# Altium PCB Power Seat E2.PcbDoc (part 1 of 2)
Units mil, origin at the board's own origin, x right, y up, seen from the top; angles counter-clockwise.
Board outline 6560 x 2560 mil, 2 copper layers (Top Layer, Bottom Layer), stack 61.4 mil thick; 98 components, 83 nets, 370 pads, 533 vias.
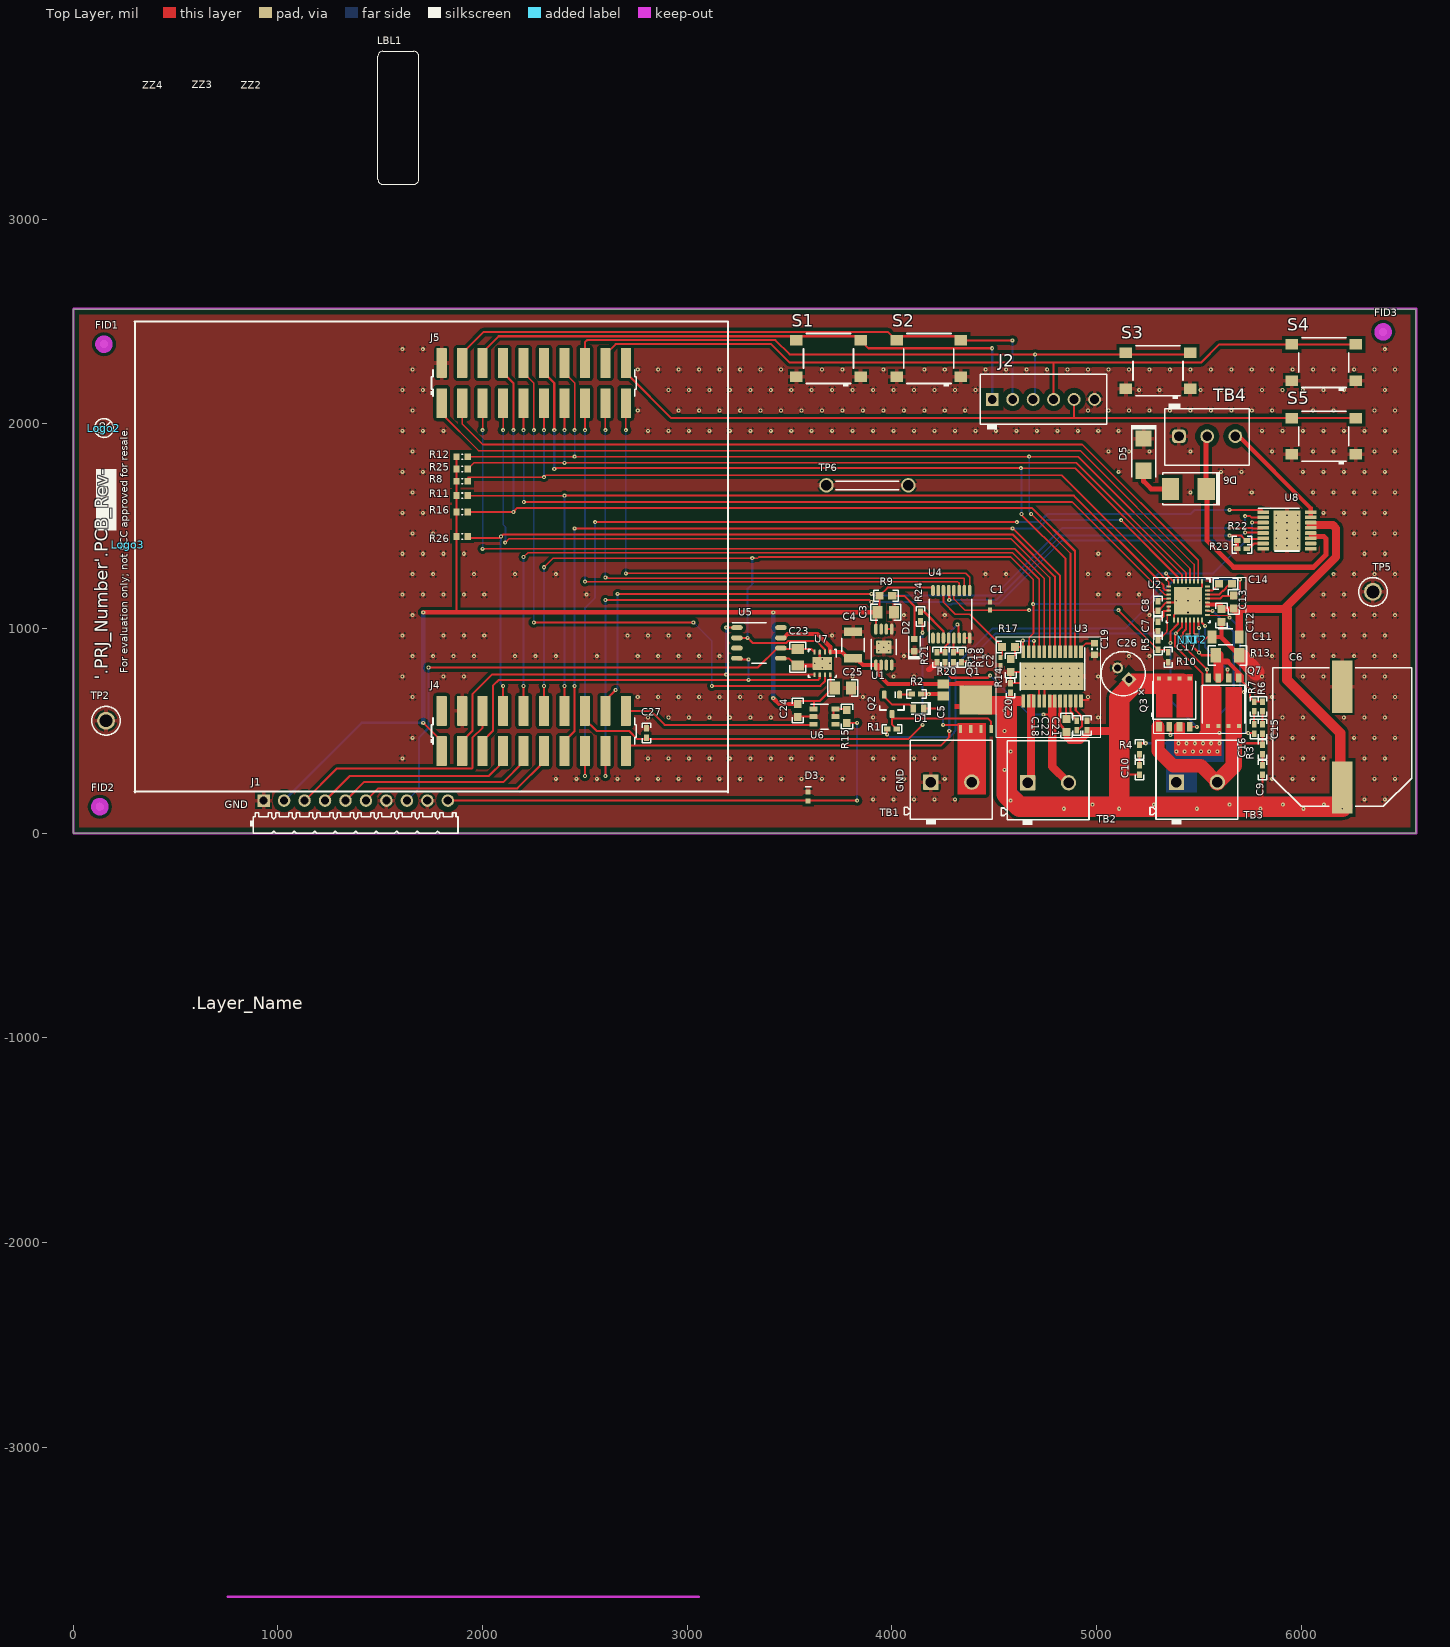
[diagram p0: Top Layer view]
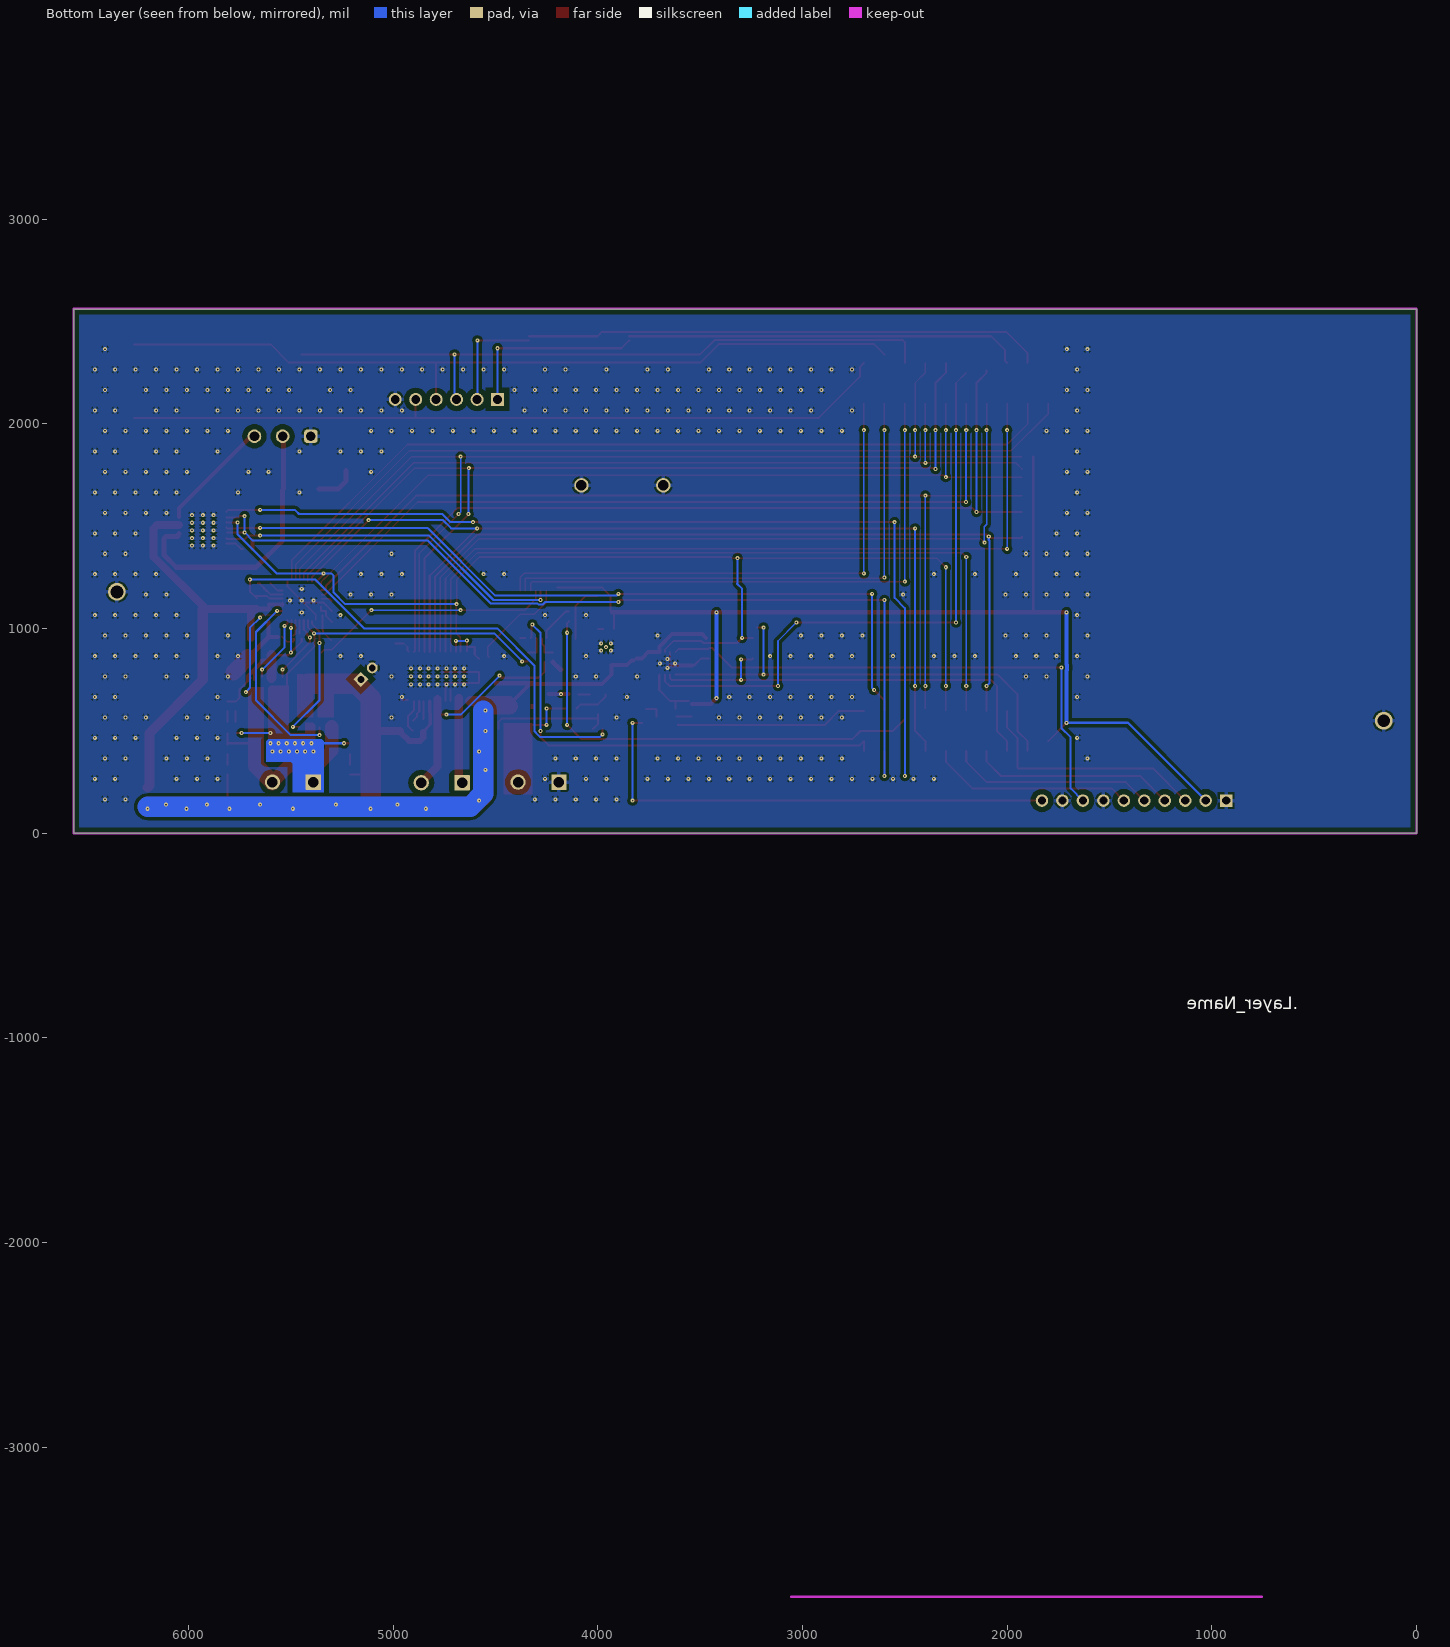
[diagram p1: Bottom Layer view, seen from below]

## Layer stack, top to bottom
Top Solder: solder mask 0.4, Solder Resist, Dk 3.5
Top Layer: signal copper 4.2
Dielectric1: core 53, FR-4, Dk 4.8
Bottom Layer: signal copper 4.2
Bottom Solder: solder mask 0.4, Solder Resist, Dk 3.5

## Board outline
0,0 0,2560 6560,2560 6560,0

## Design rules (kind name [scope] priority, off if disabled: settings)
AcuteAngle [All] p1: minimum=4.50000000000000E+0001 checktracksonly=FALSE
AssemblyTestPointUsage [All] p1: valid=2
BoardOutlineClearance BoardOutlineClearance_MountingHoles [OnCopper and InComponentClass('Mounting Holes')] p1: gap=40 ignorepadtopadclearanceinfootprint=FALSE
BoardOutlineClearance BoardOutlineClearance_Poly [OnCopper and IsPoly] p2: gap=25 ignorepadtopadclearanceinfootprint=FALSE
BoardOutlineClearance [OnCopper and Not InComponentClass('Logo') and not InComponentClass('FiducialMark') and not InRegion(1000,500,4000,800) and not InPoly] p3: gap=75 ignorepadtopadclearanceinfootprint=FALSE
Clearance Clearance_Keepouts [((IsTrack Or IsArc) And Not InPoly) And IsFree and IsKeepOut vs ((IsTrack Or IsArc) And Not InPoly) And IsFree and IsKeepOut] p1: gap=0 ignorepadtopadclearanceinfootprint=FALSE
Clearance Clearance_Poly [InPolygon] p2: gap=25 ignorepadtopadclearanceinfootprint=FALSE except(0: Arc-Hole Track-Hole SMDPad-Hole THPad-Hole Via-Hole Fill-Hole Poly-Hole Region-Hole Text-Hole; 15: Arc-Poly Track-Poly SMDPad-Poly Via-Poly Fill-Poly Poly-Poly)
Clearance [All] p3: gap=7.87 ignorepadtopadclearanceinfootprint=FALSE except(0: Arc-Hole Track-Hole SMDPad-Hole THPad-Hole Via-Hole Fill-Hole Poly-Hole Region-Hole Text-Hole)
ComponentClearance ComponentClearance_MountingHoles_FiducialMarks [InComponentClass('Mounting Holes') vs InComponentClass('FiducialMark')] p1: gap=50 collisioncheckmode=3 verticalgap=10 showdistances=FALSE
ComponentClearance ComponentClearance_Shunt [InComponentClass('Header') vs InComponentClass('Shunt')] p2: gap=0 collisioncheckmode=3 verticalgap=0 showdistances=FALSE
ComponentClearance ComponentClearance_Logo [InComponentClass('Logo')] p3: gap=50 collisioncheckmode=3 verticalgap=10 showdistances=FALSE
ComponentClearance ComponentClearance_ScrewToNut [(HasFootprint('NY PMS 440 0025 PH')) vs (HasFootprint('Keystone_1902C'))] p4: gap=5 collisioncheckmode=3 verticalgap=10 showdistances=FALSE
ComponentClearance ComponentClearance_MountingHoles [InComponentClass('Mounting Holes')] p5: gap=250 collisioncheckmode=3 verticalgap=100000 showdistances=FALSE
ComponentClearance ComponentClearance_SmallPassives [HasFootprint('0201*') or HasFootprint('0402*') or HasFootprint('0508') or HasFootprint('0603*') or HasFootprint('0612') or HasFootprint('0805*') or HasFootprint('0815*') or HasFootprint('0830*') or HasFootprint('1206*') or HasFootprint('1210*') or HasFootprint('1808*') or HasFootprint('1812*') or HasFootprint('1825*') or HasFootprint('2010*') or HasFootprint('2220*') or HasFootprint('2225*') or HasFootprint('2512*') or HasFootprint('2728*') or HasFootprint('3518*') vs HasFootprint('0201*') or HasFootprint('0402*') or HasFootprint('0508') or HasFootprint('0603*') or HasFootprint('0612') or HasFootprint('0805*') or HasFootprint('0815*') or HasFootprint('0830*') or HasFootprint('1206*') or HasFootprint('1210*') or HasFootprint('1808*') or HasFootprint('1812*') or HasFootprint('1825*') or HasFootprint('2010*') or HasFootprint('2220*') or HasFootprint('2225*') or HasFootprint('2512*') or HasFootprint('2728*') or HasFootprint('3518*')] p6: gap=14.96 collisioncheckmode=3 verticalgap=10 showdistances=FALSE
ComponentClearance ComponentClearance_THtoSMT [IsThruComponent vs IsSMTComponent] p7: gap=40 collisioncheckmode=3 verticalgap=30 showdistances=FALSE
ComponentClearance ComponentClearance_THtoTH [IsThruComponent vs IsThruComponent] p8: gap=30 collisioncheckmode=3 verticalgap=30 showdistances=FALSE
ComponentClearance [All] p9: gap=30 collisioncheckmode=3 verticalgap=10 showdistances=FALSE
DiffPairsRouting [All] p1: maxlimit=100 minlimit=10 mostfreqgap=10 toplayer_minwidth=15 toplayer_maxwidth=15 toplayer_prefwidth=15 bottomlayer_minwidth=15 bottomlayer_maxwidth=15 bottomlayer_prefwidth=15 maxuncoupledlength=1000
FabricationTestPointUsage TestPointUsage [All] p1: valid=2 allowmultiple=FALSE
FabricationTestpoint Testpoint [All] p1: side=3 testpointundercomponent=TRUE minsize=40 maxsize=100 preferedsize=60 minholesize=0 maxholesize=40 preferedholesize=32 testpointgrid=1 allowsidetop=TRUE allowsidebottom=TRUE usegrid=TRUE gridtolerance=0.01
FanoutControl Fanout_LCC [IsLCC] p1: bgadir=Out bgaviamode=Centered fanoutstyle=Auto fanoutdirection=Alternating viagrid=1 // Fanout_LCC (Default Rule)
FanoutControl Fanout_BGA [IsBGA] p2: bgadir=Out bgaviamode=Centered fanoutstyle=Auto fanoutdirection=Alternating viagrid=1 // Fanout_BGA (Default Rule)
FanoutControl Fanout_Default [All] p4: bgadir=Out bgaviamode=Centered fanoutstyle=Auto fanoutdirection=Alternating viagrid=1 // Fanout_Default (Default Rule)
FanoutControl Fanout_Small [(CompPinCount < 5)] p5: bgadir=Out bgaviamode=Centered fanoutstyle=Auto fanoutdirection=OutThenIn viagrid=1 // Fanout_Small (Default Rule)
HoleSize [All] p1: absolutevalues=TRUE maxlimit=251 minlimit=7.87 maxpercent=80.000 minpercent=20.000
MinimumAnnularRing MinimumAnnularRing_ThermalPadVias [IsVia and InAnyComponent] p1: minimumring=5.91
MinimumAnnularRing [All] p2: minimumring=5.91
MinimumSolderMaskSliver MinimumSolderMaskSliver_Logo [InComponentClass('Logo') vs InComponentClass('Logo')] p1: minsoldermaskwidth=0.7
MinimumSolderMaskSliver [All] p2: minsoldermaskwidth=3.94
PlaneClearance [All] p1: clearance=10
PlaneConnect [All] p1: planeconnectstyle=Relief reliefexpansion=10 reliefentries=4 reliefconductorwidth=10 reliefairgap=10
PolygonConnect [InNet('GND')] p1: connectstyle=Relief reliefconductorwidth=20 reliefentries=4 polygonreliefangle="90 Angle" airgapwidth=10
RoutingVias ThermalPadVias [IsVia and InAnyComponent] p1: holewidth=7.87 width=19.68 viastyle="Through Hole" minholewidth=7.87 minwidth=19.68 maxholewidth=12.99 maxwidth=23.62
RoutingVias [All] p2: holewidth=16 width=34 viastyle="Through Hole" minholewidth=7.87 minwidth=19.68 maxholewidth=40 maxwidth=65
SilkToBoardRegionClearance [Not ((IsComment or IsDesignator) And (Hide <> 'False')) and not InRegion(1000,500,4000,800)] p1:
SilkToSilkClearance SilkToSilkClearance_Pb-FreeLogo [(HasFootprint('Pb-Free_Overlay_Medium') OR HasFootprint('Pb-Free_Overlay_Small')) vs (HasFootprint('Pb-Free_Overlay_Medium') OR HasFootprint('Pb-Free_Overlay_Small'))] p1: silktosilkclearance=0
SilkToSilkClearance [All] p2: silktosilkclearance=4
SilkToSolderMaskClearance SilkToComponentPadClearance [(IsPad or IsFill or IsRegion) and InAnycomponent] p1: minsilkscreentomaskgap=5 clearancetoexposedcopper=TRUE
SilkToSolderMaskClearance "Silk to Solder Mask Opening" [All] p2: minsilkscreentomaskgap=4 clearancetoexposedcopper=FALSE
SolderMaskExpansion [All] p1: expansion=1.97
Width [All] p1: maxlimit=100 minlimit=6 preferedwidth=10 checkconnectedcopper=TRUE
14 further rules are at their usual default settings.

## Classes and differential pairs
component class Header: J1 J4 J5
component class "Power Seat Logic E2": !PCB1 C23 C24 C25 C27 D3 FID1 FID2 FID3 J1 J2 J4 J5 LBL1 Logo2 Logo3 R15 R18 R19 R20 R21 R24 S1 S2 S3 S4 S5 TP6 U4 U5 U6 U7 ZZ1 ZZ2 ZZ3 ZZ4
component class "Power Seat Motor Drives E2": C1 C2 C3 C4 C5 C6 C7 C8 C9 C10 C11 C12 C13 C14 C15 C16 C17 C18 C19 C20 C21 C22 C26 C? D1 D2 D5 D6 H1 H2 NT1 NT2 Q1 Q2 Q3 Q5 Q7 R1 R2 R3 R4 R5 R6 R7 R8 R9 R10 R11 R12 R13 R14 R16 R17 R22 R23 R25 R26 R? TB1 TB2 TB3 TB4 TP1 TP2 TP3 TP4 TP5 U1 U2 U3 U8 U?
component class FiducialMark: FID1 FID2 FID3 FID?
component class AssemblyNote: ZZ1 ZZ2 ZZ3 ZZ4 ZZ?
component class Label: LBL1

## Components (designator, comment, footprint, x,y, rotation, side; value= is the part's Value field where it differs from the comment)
C1 "GRM155R71C102KA01D" 0402L 4480,1110 r90 top value=1000pF
C2 "GRM155R71C102KA01D" 0402L 4530,840 r270 top value=1000pF
C3 "C2012X7R1A475M125AC" 0805_HV 3970,1080 r0 top value=4.7uF
C4 "UMK325AB7106KMHT" 1210_280 3810,920 r90 top value=10uF
C5 "GRM21BR71H105KA12L" 0805L 4250,700 r270 top value=1uF
C6 "EEV-FK1H681M" SM_RADIAL_J16 6200,470 r90 top value=680uF
C7 "GRM155R70J105MA12D" 0402 5300,1010 r270 top value=1uF
C8 "GRM155R70J105MA12D" 0402 5300,1110 r270 top value=1uF
C9 "CGA2B3X8R1H103K050BB" 0402 5810,310 r90 top value=0.01uF
C10 "CGA2B3X8R1H103K050BB" 0402 5210,310 r90 top value=0.01uF
C11 "CL31B106KBHNNNE" 1206_180 5630,960 r180 top value=10uF
C12 "C1608X7R1H104K080AA" 0603 5610,1063.46 r270 top value=0.1uF
C13 "C1608X7R1C105K080AC" 0603 5670,1130 r270 top value=1uF
C14 "C1608X7R1H104K080AA" 0603 5630,1220 r180 top value=0.1uF
C15 "CGA2B3X8R1H103K050BB" 0402 5810,510 r90 top value=0.01uF
C16 "CGA2B3X8R1H103K050BB" 0402 5770,510 r90 top value=0.01uF
C17 "GRM155R71C102KA01D" 0402L 5466.73,966.73 r0 top value=1000pF
C18 "EMK107B7105KA-T" 0603 4853,527 r270 top value=1uF
C19 "GRM188R70J105KA01D" 0603L 4990,900 r90 top value=1uF
C20 "CGA2B3X7R1H104M050BB" 0402 4580,710 r90 top value=0.1uF
C21 "CGA2B3X7R1H104M050BB" 0402 4953,527 r90 top value=0.1uF
C22 "CGA2B3X7R1H473K050BB" 0402 4903,527 r270 top value=0.047uF
C23 "C0805C221K5RACTU" 0805_HV 3540,860 r90 top value=220pF
C24 "LMK107B7105KAHT" 0603 3540,600 r270 top value=1uF
C25 "C2012X7R1A475M125AC" 0805_HV 3760,710 r0 top value=4.7uF
C26 "ECA1HM220" Panasonic_500x1100 5130,780 r135 top value=22uF
C27 "GRM155R70J105MA12D" 0402 2800,490 r90 top value=1uF
D1 "CD0603-S0180" Diode_0603 4130,610 r180 top value=90V
D2 "LTST-C191KFKT" LTST-C191_Orange 4110,920 r270 top value=Orange
D3 "LW QH8G-Q2S2-3K5L-1" "LW QH8G_White" 3590,180 r90 top value=White
D5 "1SMA18AT3G" SMA 5230,1850 r270 top value=18V
D6 "ES2D" SMB 5448,1683.18 r180 top value=200V
FID1 "Fiducial" Fiducial10-20 150,2390 r90 top
FID2 "Fiducial" Fiducial10-20 130,130 r90 top
FID3 "Fiducial" Fiducial10-20 6400,2450 r90 top
J1 "TSW-110-08-T-S-RA" Samtec_TSW-110-08-x-S-RA 1380,160 r0 top
J2 "1725698" Phoenix_1725698 4740,2120 r0 top
J4 "TSM-110-01-L-DV-P" CONN_TSM-110-01-T-DV-P 2250,500 r90 top
J5 "TSM-110-01-L-DV-P" CONN_TSM-110-01-T-DV-P 2250,2200 r90 top
LBL1 "Size: 0.65\" x 0.20 \"" Label_650x200 1588,3496 r90 top
Logo2 "Pb-Free Symbol" Pb-Free_Overlay_Small 150,1980 r90 top
Logo3 "FCC disclaimer" FCC_disclaimer 265,1410 r90 top
NT1 "Net-Tie" Net-Tie_10mil 5446.73,946.73 r90 top net-tie
NT2 "Net-Tie" Net-Tie_10mil 5486.73,946.73 r270 top net-tie
Q1 "SQJA04EP-T1_GE3" PowerPAK_SO-8L 4410,620 r90 top value=60V
Q2 "MMBTA05LT1G" SOT-23 4000,630 r270 top value="60 V"
Q3 "BUK9K6R2-40E,115" SOT1205 5380,650 r90 top value=40V
Q7 "BUK9K6R2-40E,115" SOT1205 5620,630 r270 top value=40V
R1 "CRCW040210K0JNED" 0402 4000,510 r180 top value=10k
R2 "CRCW040243K0JNED" 0402 4120,680 r180 top value=43k
R3 "CRCW0402100RFKED" 0402 5810,410 r270 top value=100
R4 "CRCW0402100RFKED" 0402 5210,410 r270 top value=100
R5 "CRCW04023K74FKED" 0402 5300,920 r270 top value=3.74k
R6 "CRCW0402100RFKED" 0402 5810,620 r270 top value=100
R7 "CRCW0402100RFKED" 0402 5770,620 r270 top value=100
R8 "CRCW060310K0JNEA" 0603L 1900,1720 r180 top value=10k
R9 "CRCW0603200RJNEA" 0603 3970,1160 r0 top value=200
R10 "RC0402FR-0710KL" 0402 5350,860 r90 top value=10.0k
R11 "CRCW060310K0JNEA" 0603L 1900,1650 r0 top value=10k
R12 "RC0603JR-07750RL" 0603L 1900,1840 r180 top value=750
R13 "CSNL1206FT3L00" 1206 5640,870 r180 top value=0.003
R14 "RC0603FR-07330RL" 0603 4580,820 r90 top value=330
R15 "CRCW060310R0JNEAHP" 0603 3780,570 r270 top value=10
R16 "CRCW060310K0JNEA" 0603L 1900,1570 r0 top value=10k
R17 "CRCW060310K0FKEA" 0603 4570,910 r0 top value=10.0k
R18 "CRCW0402120KJNED" 0402 4340,860 r270 top value=120k
R19 "CRCW040210K0JNED" 0402 4300,860 r90 top value=10k
R20 "CRCW0402120KJNED" 0402 4260,860 r270 top value=120k
R21 "CRCW040210K0JNED" 0402 4220,860 r90 top value=10k
R22 "CRCW0402294RFKED" 0402 5710,1430 r180 top value=294
R23 "CRCW0402294RFKED" 0402 5710,1390 r0 top value=294
R24 "CRCW040210K0JNED" 0402 4140,1060 r90 top value=10k
R25 "CRCW060310K0JNEA" 0603L 1900,1780 r180 top value=10k
R26 "CRCW060310K0JNEA" 0603L 1900,1450 r0 top value=10k
S1 "430182080816" SW_430182080816 3690,2320 r180 top
S2 "430182080816" SW_430182080816 4180,2320 r180 top
S3 "430182080816" SW_430182080816 5300,2260 r180 top
S4 "430182080816" SW_430182080816 6110,2300 r180 top
S5 "430182080816" SW_430182080816 6110,1940 r180 top
TB1 "1715721" PhoenixContact_1715721 4290,250 r0 top
TB2 "1715721" PhoenixContact_1715721 4763,247 r0 top
TB3 "1715721" PhoenixContact_1715721 5490,250 r0 top
TB4 "OSTTE030161" On-Shore_OSTTE030161 5540,1940 r0 top
TP2 "5006" Keystone5006 160,550 r90 top value=Black
TP5 "5006" Keystone5006 6350,1180 r90 top value=Black
TP6 "D3082-05" Harwin_D3082-05 3880,1700 r180 top
U1 "TPS7B8233QDGNRQ1" DGN0008D_N 3960,910 r90 top
U2 "DRV8703QRHBRQ1" RHB0032E 5446.73,1136.73 r270 top
U3 "DRV8873SPWPRQ1" PWP0024J_M 4783,767 r270 top
U4 "SN74LV4051AQPWRQ1" PW0016A_N 4290,1070 r90 top
U5 "TLIN1029DQ1" D0008A_N 3350,930 r0 top
U6 "TPS22810DBVR" DBV0006A_N 3670,570 r0 top
U7 "TLIN1028DRB" DRB0008F 3660,830 r270 top
U8 "TPS2H160BQPWPRQ1" PWP0016J_N 5930,1480 r0 top
ZZ1 "This Assembly Note is for PCB labels only" AssemblyNoteLabel 7710,210 r90 top
ZZ2 "These assemblies are ESD sensitive, ESD precautions shall be observed." AssemblyNote 838,3586 r90 top
ZZ3 "These assemblies must be clean and free from flux and all contaminants. Use of no clean flux is not acceptable." AssemblyNote 598,3586 r90 top
ZZ4 "These assemblies must comply with workmanship standards IPC-A-610 Class 2, unless otherwise specified." AssemblyNote 358,3586 r90 top

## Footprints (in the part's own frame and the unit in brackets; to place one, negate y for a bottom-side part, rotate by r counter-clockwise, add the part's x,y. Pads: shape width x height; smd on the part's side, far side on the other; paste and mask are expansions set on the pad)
0402 [mm] "0402 from SM-752 data"
  rect 0.8x0.6 smd: 1(-0.6,0) 2(0.6,0)
  silkscreen extent -1.22,-0.52 1.22,0.52, body extent -0.55,-0.3 0.55,0.3, height 0.6
0402L [mm] "0402 from SM-752 data"
  rect 0.6x0.5 smd: 1(-0.5,0) 2(0.5,0)
  body extent -0.55,-0.3 0.55,0.3, height 0.6
0603 [mm] "0603 from SM-752 data"
  rect 1x0.95 smd: 1(-0.8,0) 2(0.8,0)
  silkscreen extent -1.52,-0.69 1.52,0.69, body extent -0.87,-0.47 0.87,0.47, height 1
0603L [mm] "0603 from SM-752 data"
  rect 0.8x0.85 smd: 1(-0.7,0) 2(0.7,0)
  silkscreen extent -0.07,-0.33 0.07,0.33, body extent -0.87,-0.47 0.87,0.47, height 1
0805_HV [mil] "0805 with 30mil clearance between pads"
  rect 50x63 smd: 1(-40,0) 2(40,0)
  silkscreen extent -74,-40 74,40, body extent -43,-29 43,29, height 57
0805L [mm] "0805 from SM-752 data"
  rect 1.1x1.4 smd: 1(-0.75,0) 2(0.75,0)
  body extent -1.1,-0.72 1.1,0.72, height 1.45
1206 [mm] "1206 from SM-752 data"
  rect 1.3x1.85 smd: 1(-1.45,0) 2(1.45,0)
  silkscreen extent -2.4,-1.21 2.4,1.21, body extent -1.7,-0.9 1.7,0.9, height 1.35
1206_180 [mm] "1206_180"
  rect 1.1x1.6 smd: 1(-1.7,0) 2(1.7,0)
  silkscreen extent -0.9,-1 0.9,1, body extent -1.75,-0.95 1.75,0.95, height 1.8
1210_280 [mm] "SMD, 2-Leads, Body 3.6x2.8mm, Height 2.8mm"
  rect 1.1x2.2 smd: 1(-1.65,0) 2(1.65,0)
  silkscreen extent -0.84,-1.4 0.84,1.4, body extent -1.8,-1.4 1.8,1.4, height 2.8
AssemblyNote [mil] "Assembly Note"
AssemblyNoteLabel [mil] "Assembly Note for PCB Labels"
CONN_TSM-110-01-T-DV-P [mil]
  rrect8% 145x50 smd: 1(-98,450) 2(98,450) 3(-98,350) 4(98,350) 5(-98,250) 6(98,250) 7(-98,150) 8(98,150) 9(-98,50) 10(98,50) 11(-98,-50) 12(98,-50) 13(-98,-150) 14(98,-150) 15(-98,-250) 16(98,-250) 17(-98,-350) 18(98,-350) 19(-98,-450) 20(98,-450)
  silkscreen extent -65,-500 65,506, body extent -145,-500 145,500, height 380
D0008A_N [mm] "SOIC, 8-Leads, Body 4.9x3.9mm, Pitch 1.27mm, IPC Medium Density"
  oval 1.45x0.6 smd: 1(-2.725,1.905) 2(-2.725,0.635) 3(-2.725,-0.635) 4(-2.725,-1.905) 5(2.725,-1.905) 6(2.725,-0.635) 7(2.725,0.635) 8(2.725,1.905)
  silkscreen extent -3.3,-2.5 0.9,2.5, body extent -3,-2.45 3,2.45, height 1.63
DBV0006A_N [mm] "SOT23, 6-Leads, Body 2.9x1.6mm, Pitch 0.95mm, Lead Span 2.8mm, IPC Medium Density"
  rrect17% 1x0.6 smd: 1(-1.375,0.95) 2(-1.375,0) 3(-1.375,-0.95) 4(1.375,-0.95) 5(1.375,0) 6(1.375,0.95)
  silkscreen extent -1.68,-1.55 0.5,1.55, body extent -1.42,-1.46 1.42,1.46, height 1.12
DGN0008D_N [mm] "TSOP, 8-Leads, Body 3x3mm, Pitch 0.65mm, Thermal Pad 1.89x1.57mm, IPC Medium Density"
  rrect100% 1.35x0.45 smd: 1(-2.225,0.975) 2(-2.225,0.325) 3(-2.225,-0.325) 4(-2.225,-0.975) 5(2.225,-0.975) 6(2.225,-0.325) 7(2.225,0.325) 8(2.225,0.975)
  rrect6% 1.57x1.89 smd: 9(0,0)
  silkscreen extent -2.73,-1.55 0.95,1.55, body extent -2.46,-1.5 2.46,1.5, height 1.1
Diode_0603 [mm] "Based on Bourns recommended land pattern Rev 10/09"
  rect 0.7x1 smd: 1(-0.65,0) 2(0.65,0)
  silkscreen extent -1.5,-0.8 0.9,0.8, body extent -0.9,-0.5 0.9,0.5, height 0.85
DRB0008F [mm] "SON, 8-Leads, Body 3x3mm, Pitch 0.65mm, Thermal Pad 2.4x1.6mm, TI Recommended"
  rrect33% 0.6x0.3 smd: 1(-1.4,0.975) 2(-1.4,0.325) 3(-1.4,-0.325) 4(-1.4,-0.975) 5(1.4,-0.975) 6(1.4,-0.325) 7(1.4,0.325) 8(1.4,0.975)
  rrect9% 1.47x1.07 on Top Paste: 9(0,0.635) 9(0,-0.635)
  rrect6% 1.6x2.4 smd paste-1.2: 9(0,0)
  silkscreen extent -1.73,-1.73 1.73,1.73, body extent -1.5,-1.5 1.5,1.5, height 0.77
FCC_disclaimer [mil]
Fiducial10-20 [mm]
  round 1 smd mask+0.5: 1(0,0)
  Top Layer keep-out circle w1.178: c0,0 r0.5
Harwin_D3082-05 [mm] "Shorting Plug, 10.16mm spacing, TH"
  round 1.8 hole 1.3: 1(-5.08,0) 2(5.08,0)
  silkscreen extent -3.9,-0.53 3.9,0.53, body extent -5.6,-0.52 5.61,0.52, height 6.63
Keystone5006 [mil] "Keystone Compact loops"
  round 87 hole 63: 1(0,0)
  silkscreen extent -70,-70 70,70, body extent -63,-63 62,63, height 225
Label_650x200 [mil] "Thermal Transfer Label"
  round 1 on Mech13: 0(0,0)
  silkscreen extent -325,-100 325,100, body extent -325,-100 325,100, height 1
LTST-C191_Orange [mm] "SMD, 2-Leads, Body 1.6x0.8mm"
  rect 0.8x0.8 smd: 1(-0.75,0) 2(0.75,0)
  silkscreen extent -1.1,-0.8 1.8,0.8, body extent -0.85,-0.45 0.85,0.45, height 0.65
"LW QH8G_White" [mm] "SMD, 2-Leads, Body 1x0.5mm"
  rect 0.6x0.6 smd paste-0.3: 1(-0.55,0) 2(0.55,0)
  silkscreen extent 1.1,-0.4 1.3,0.4, body extent -0.55,-0.3 0.55,0.3, height 0.4
Net-Tie_10mil [mil] "10mil net tie, no solder mask opening, no solder paste"
  rect 10x10 smd paste-5 mask-5: 1(-10,0) 2(10,0)
  Top Layer region: -6,5 6,5 6,-5 -6,-5
On-Shore_OSTTE030161 [mm] "Terminal Block, 3.5mm, 3x1, TH"
  rrect50% 1.7x1.7 hole 1.2: 1(-3.5,0)
  round 1.7 hole 1.2: 2(0,0) 3(3.5,0)
  silkscreen extent -5.25,-3.6 5.25,4.05, body extent -5.75,-3.6 5.75,3.4, height 8.4
Panasonic_500x1100 [mm] "TH, 2-Leads, Dia 5mm,  Lead Spacing 2mm"
  rect 1.35x1.35 hole 0.85: 1(-1,0)
  round 1.35 hole 0.85: 2(1,0)
  silkscreen extent -2.75,-2.75 2.75,2.75, body extent -2.73,-2.75 2.75,2.75, height 12.51
Pb-Free_Overlay_Small [mil]
  silkscreen extent -46,-46 46,46
Phoenix_1725698 [mm] "Terminal Block, 6x1, 2.54mm, TH"
  rect 1.6x1.6 hole 1.1: 1(-6.35,0)
  round 1.6 hole 1.1: 2(-3.81,0) 3(-1.27,0) 4(1.27,0) 5(3.81,0) 6(6.35,0)
  silkscreen extent -7.85,-3.75 7.85,3.1, body extent -7.85,-3.1 7.85,3.1, height 8.51
PhoenixContact_1715721 [mm] "Phoenix Contact 1715721 used on LM3445 design from Longmont"
  rrect5% 1.905x1.905 hole 1.3: 1(-2.54,0)
  round 1.9 hole 1.3: 2(2.54,0)
  silkscreen extent -5.82,-5.25 5.08,5.2, body extent -5.82,-4.6 5.08,5.2, height 14.2
PowerPAK_SO-8L [mm] "based on Vishay recommended land pattern Document 63818 Feb 7, 2012"
  rect 1x0.41 smd: 1(-2.805,1.905) 2(-2.805,0.635) 3(-2.805,-0.635) 4(-2.805,-1.905)
  rect 3.63x4.061 smd: 5(0.805,0)
  Top Layer region: -0.297,-2.64 0.298,-2.64 0.298,-2.03 -0.297,-2.03
  Top Layer region: -0.297,2.03 0.298,2.03 0.298,2.64 -0.297,2.64
  Top Layer region: 2.615,-2.5 3.125,-2.5 3.125,2.5 2.615,2.5
  body extent -3.07,-2.57 3.08,2.57, height 1.21
PW0016A_N [mm] "TSOP, 16-Leads, Body 5x4.4mm, Pitch 0.65mm, IPC Medium Density"
  oval 1.4x0.45 smd: 1(-2.95,2.275) 2(-2.95,1.625) 3(-2.95,0.975) 4(-2.95,0.325) 5(-2.95,-0.325) 6(-2.95,-0.975) 7(-2.95,-1.625) 8(-2.95,-2.275) 9(2.95,-2.275) 10(2.95,-1.625) 11(2.95,-0.975) 12(2.95,-0.325) 13(2.95,0.325) 14(2.95,0.975) 15(2.95,1.625) 16(2.95,2.275)
  silkscreen extent -3.5,-2.55 1.85,2.75, body extent -3.21,-2.5 3.21,2.5, height 1
PWP0016J_N [mm] "TSOP, 16-Leads, Body 5x4.4mm, Pitch 0.65mm, Exposed Pad, IPC Medium Density"
  rrect22% 1.4x0.45 smd: 1(-2.95,2.275) 2(-2.95,1.625) 3(-2.95,0.975) 4(-2.95,0.325) 5(-2.95,-0.325) 6(-2.95,-0.975) 7(-2.95,-1.625) 8(-2.95,-2.275) 9(2.95,-2.275) 10(2.95,-1.625) 11(2.95,-0.975) 12(2.95,-0.325) 13(2.95,0.325) 14(2.95,0.975) 15(2.95,1.625) 16(2.95,2.275)
  rrect6% 3.4x5 smd paste-1.7 mask-1.7: 17(0,0)
  rrect4% 2.46x3.55 on Top Solder: 17(0,0)
  rrect4% 2.46x3.55 on Top Paste: 17(0,0)
  silkscreen extent -3.55,-2.55 1.5,2.75, body extent -3.2,-2.5 3.2,2.5, height 1.13
PWP0024J_M [mm] "TSOP, 24-Leads, Body 7.9x4.5mm (max), Pitch 0.65mm, IPC Low Density"
  rrect22% 1.6x0.45 smd: 1(-3.05,3.575) 2(-3.05,2.925) 3(-3.05,2.275) 4(-3.05,1.625) 5(-3.05,0.975) 6(-3.05,0.325) 7(-3.05,-0.325) 8(-3.05,-0.975) 9(-3.05,-1.625) 10(-3.05,-2.275) 11(-3.05,-2.925) 12(-3.05,-3.575) 13(3.05,-3.575) 14(3.05,-2.925) 15(3.05,-2.275) 16(3.05,-1.625) 17(3.05,-0.975) 18(3.05,-0.325) 19(3.05,0.325) 20(3.05,0.975) 21(3.05,1.625) 22(3.05,2.275) 23(3.05,2.925) 24(3.05,3.575)
  rrect6% 3.4x7.8 smd paste-2 mask-2: 25(0,0)
  rrect3% 3.2x5.26 on Top Solder mask+0.085: 25(0,0)
  rrect3% 3.2x5.26 on Top Paste mask+0.085: 25(0,0)
  silkscreen extent -3.55,-3.95 1.7,4.05, body extent -3.21,-3.9 3.21,3.9, height 1.2
RHB0032E [mm] "QFN, 32-Leads, Body 5x5mm, Pitch 0.5mm, Thermal Pad 3.45x3.45mm, TI Recommended"
  rrect40% 0.6x0.25 smd: 1(-2.4,1.75) 2(-2.4,1.25) 3(-2.4,0.75) 4(-2.4,0.25) 5(-2.4,-0.25) 6(-2.4,-0.75) 7(-2.4,-1.25) 8(-2.4,-1.75) 17(2.4,-1.75) 18(2.4,-1.25) 19(2.4,-0.75) 20(2.4,-0.25) 21(2.4,0.25) 22(2.4,0.75) 23(2.4,1.25) 24(2.4,1.75)
  rrect40% 0.25x0.6 smd: 9(-1.75,-2.4) 10(-1.25,-2.4) 11(-0.75,-2.4) 12(-0.25,-2.4) 13(0.25,-2.4) 14(0.75,-2.4) 15(1.25,-2.4) 16(1.75,-2.4) 25(1.75,2.4) 26(1.25,2.4) 27(0.75,2.4) 28(0.25,2.4) 29(-0.25,2.4) 30(-0.75,2.4) 31(-1.25,2.4) 32(-1.75,2.4)
  rrect3% 3.45x3.45 smd paste-1.725: 33(0,0)
  rrect7% 1.49x1.49 on Top Paste: ""(-0.845,0.845) ""(-0.845,-0.845) ""(0.845,0.845) ""(0.845,-0.845)
  silkscreen extent -2.72,-2.73 2.72,2.73, body extent -2.57,-2.57 2.58,2.58, height 1.01
Samtec_TSW-110-08-x-S-RA [mm] "Header, 2.54mm, 10x1, R/A, TH"
  rect 1.55x1.55 hole 1.02: 1(-11.43,0)
  round 1.55 hole 1.02: 2(-8.89,0) 3(-6.35,0) 4(-3.81,0) 5(-1.27,0) 6(1.27,0) 7(3.81,0) 8(6.35,0) 9(8.89,0) 10(11.43,0)
  silkscreen extent -13.1,-4.06 12.7,-1.52, body extent -12.7,-9.9 12.7,0.32, height 3.02
SM_RADIAL_J16 [mm] "16 x 16.5mm:  Panasonic J16"
  rect 6.5x2.5 smd: 1(-6.25,0) 2(6.25,0)
  silkscreen extent -8.6,-8.6 8.6,8.6, body extent -8.6,-8.6 8.6,8.6, height 17
SMA [mm] "Molded Diode, 2-Leads, Body 4.3x2.6mm, IPC Medium Density, based on OnSemi component dimensions and land pattern"
  rect 2x2 smd: 1(-2,0) 2(2,0)
  silkscreen extent -3.66,-1.57 2.79,1.57, body extent -2.6,-1.3 2.6,1.3, height 2.42
SMB [mil] "Molded Diode, 2-Leads, Body 5.4x3.6mm, IPC Medium Density, based on OnSemi component dimensions"
  rect 85x107.99 smd: 1(-87.01,0) 2(87.01,0)
  silkscreen extent -155,-82 125,82, body extent -106,-71 106,71, height 91
SOT1205 [mm] "SMD, 8-Leads, Body 4.575x5.125mm, Pitch 1.27mm"
  rect 1.15x0.7 smd paste-0.025 mask+0.062: 1(-3.275,1.905) 2(-3.275,0.635) 3(-3.275,-0.635) 4(-3.275,-1.905)
  rect 0.5x0.5 smd: 5(2.7,-1.905) 6(2.7,-0.635) 7(2.7,0.635) 8(2.7,1.905)
  Top Layer region: -2.1,-2.255 3.2,-2.255 3.2,-1.555 2,-1.555 2,-0.985 3.2,-0.985 3.2,-0.285 -2.1,-0.285
  Top Layer region: -2.1,2.255 3.2,2.255 3.2,1.555 2,1.555 2,0.985 3.2,0.985 3.2,0.285 -2.1,0.285
  silkscreen extent -2.35,-2.65 2.35,2.9, body extent -3.7,-2.65 2.9,2.65, height 1.06
SOT-23 [mm] "SOT23, 3-Leads, Body 2.9x1.3mm, Pitch 0.95mm, Lead Span 2.5mm, IPC Medium Density"
  rrect50% 1x0.6 smd: 1(-1.2,0.95) 2(-1.2,-0.95) 3(1.2,0)
  silkscreen extent -1.63,-1.5 0.7,1.5, body extent -1.16,-1.45 1.21,1.45, height 1
SW_430182080816 [mm] "SMD, 4-Leads, Body 6.2x6.2mm"
  rect 1.55x1.3 smd: 1(-3.975,2.25) 2(-3.975,-2.25) 3(3.975,2.25) 4(3.975,-2.25)
  silkscreen extent -3.1,-3.1 3.1,3.5, body extent -4.5,-3.1 4.5,3.1, height 8

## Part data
C1 C2 C17: "CAP, CERM, 1000 pF, 16 V, +/- 10%, X7R, 0402", Cap_Case=0402, Manufacturer=MuRata, Supplier Part Number 1=GRM155R71C102KA01D-ND, TempCo=X7R, Tolerance_%=10, Value1=Unknown, Value2=16V, ValueDisplayed=1000pF
C3 C25: "CAP, CERM, 4.7 µF, 10 V,+/- 20%, X7R, 0805", Cap_Case=0805, Manufacturer=TDK, Supplier Part Number 1=445-1605-1-ND, TempCo=X7R, Tolerance_%=20, Value2=10V, ValueDisplayed=4.7µF
C4: "CAP, CERM, 10 µF, 50 V,+/- 10%, X7R, AEC-Q200 Grade 1, 1210", Cap_Case=1210, Manufacturer="Taiyo Yuden", Supplier Part Number 1=587-4326-1-ND, TempCo=X7R, Tolerance_%=10, Value2=50V, ValueDisplayed=10µF
C5: "CAP, CERM, 1 µF, 50 V, +/- 10%, X7R, 0805", Cap_Case=0805, Manufacturer=MuRata, Supplier Part Number 1=490-4736-1-ND, TempCo=X7R, Tolerance_%=10, Value1=Unknown, Value2=50V, ValueDisplayed=1µF
C6: library part CMP-0011212-2, "CAP, AL, 680 uF, 50 V, +/- 20%, 0.073 ohm, AEC-Q200 Grade 2, SMD", Cap_Case=J16, Manufacturer=Panasonic, Supplier Part Number 1=PCE3523CT-ND, Tolerance_%=20%, Value1="0.073 ohm", Value2=50V, ValueDisplayed=680uF
C7 C8 C27: library part CMP-0006624-2, "CAP, CERM, 1 uF, 6.3 V, +/- 20%, X7R, 0402", Cap_Case=0402, Manufacturer=MuRata, Supplier Part Number 1=490-9665-1-ND, TempCo=X7R, Tolerance_%=20%, Value1=Unknown, Value2=6.3V, ValueDisplayed=1uF
C9 C10 C15 C16: library part CMP-0078224-1, "CAP, CERM, 0.01 µF, 50 V,+/- 10%, X8R, AEC-Q200 Grade 0, 0402", Cap_Case=0402, Manufacturer=TDK, Supplier Part Number 1=445-12303-1-ND, TempCo=X8R, Tolerance_%=10%, Value2=50V, ValueDisplayed=0.01µF
C11: library part CMP-0008802-2, "CAP, CERM, 10 uF, 50 V, +/- 10%, X7R, 1206", Cap_Case=1206, Manufacturer=Samsung, Supplier Part Number 1=1276-6767-1-ND, TempCo=X7R, Tolerance_%=10%, Value1=Unknown, Value2=50V, ValueDisplayed=10uF
C12 C14: library part CMP-0007044-5, "CAP, CERM, 0.1 uF, 50 V, +/- 10%, X7R, 0603", Cap_Case=0603, Manufacturer=TDK, Supplier Part Number 1=445-1314-1-ND, TempCo=X7R, Tolerance_%=10%, Value1="0.0296 ohm", Value2=50V, ValueDisplayed=0.1uF
C13: library part CMP-0007037-4, "CAP, CERM, 1 uF, 16 V, +/- 10%, X7R, 0603", Cap_Case=0603, Manufacturer=TDK, Supplier Part Number 1=445-1604-1-ND, TempCo=X7R, Tolerance_%=10%, Value1="0.0057 ohm", Value2=16V, ValueDisplayed=1uF
C18: library part CMP-0007120-4, "CAP, CERM, 1 uF, 16 V, +/- 10%, X7R, 0603", Cap_Case=0603, Manufacturer="Taiyo Yuden", Supplier Part Number 1=1683647, TempCo=X7R, Tolerance_%=10%, Value1=Unknown, Value2=16V, ValueDisplayed=1uF
C19: "CAP, CERM, 1 µF, 6.3 V, +/- 10%, X7R, 0603", Cap_Case=0603, Manufacturer=MuRata, Supplier Part Number 1=490-3898-1-ND, TempCo=X7R, Tolerance_%=10, Value1=Unknown, Value2=6.3V, ValueDisplayed=1µF
C20 C21: library part CMP-0006326-2, "CAP, CERM, 0.1 uF, 50 V, +/- 20%, X7R, AEC-Q200 Grade 1, 0402", Cap_Case=0402, Manufacturer=TDK, Supplier Part Number 1=445-12271-1-ND, TempCo=X7R, Tolerance_%=20%, Value1=Unknown, Value2=50V, ValueDisplayed=0.1uF
C22: library part CMP-0006330-2, "CAP, CERM, 0.047 uF, 50 V, +/- 10%, X7R, AEC-Q200 Grade 1, 0402", Cap_Case=0402, Manufacturer=TDK, Supplier Part Number 1=445-6897-1-ND, TempCo=X7R, Tolerance_%=10%, Value1="0.06407 ohm", Value2=50V, ValueDisplayed=0.047uF
C23: library part CMP-0007764-2, "CAP, CERM, 220 pF, 50 V, +/- 10%, X7R, 0805", Cap_Case=0805, Manufacturer=Kemet, Supplier Part Number 1=399-1138-1-ND, TempCo=X7R, Tolerance_%=10%, Value1="1.414 ohm", Value2=50V, ValueDisplayed=220pF
C24: library part CMP-0007505-4, "CAP, CERM, 1 uF, 10 V, +/- 10%, X7R, AEC-Q200 Grade 1, 0603", Cap_Case=0603, Manufacturer="Taiyo Yuden", Supplier Part Number 1=587-3410-1-ND, TempCo=X7R, Tolerance_%=10%, Value1=Unknown, Value2=10V, ValueDisplayed=1uF
C26: library part CMP-0064895-2, "CAP, AL, 22 uF, 50 V, +/- 20%, TH", Cap_Case=5x11, Manufacturer=Panasonic, Supplier Part Number 1=P5179-ND, Tolerance_%=20%, Value1=Unknown, Value2=50V, ValueDisplayed=22uF
D1: library part CMP-0029009-1, "Diode, Switching, 90 V, 0.1 A, 0603 Diode", Manufacturer=Bourns, Supplier Part Number 1=652-CD0603-S0180, Value1=0.1A, Value2=1V
D2: "LED, Orange, SMD", Color=Orange, Manufacturer=Lite-On, Power_TotalModule=0.075, Supplier Part Number 1=160-1445-1-ND, Value1=0.075W, Value2=2V
D3: library part CMP-0002919-1, "LED, White, SMD", Color=White, Manufacturer=OSRAM, Supplier Part Number 1="LW QH8G-Q2S2-3K5L-1-ND", Value1=W, Value2=2.8V
D5: library part CMP-0005446-2, "Diode, TVS, Uni, 18 V, 29.2 Vc, AEC-Q101, SMA", Manufacturer=Littelfuse, Power_W=1.5W, Supplier Part Number 1=1SMA18AT3GOSCT-ND
D6: library part CMP-0029161-1, "Diode, Fast Rectifier, 200 V, 2 A, SMB", Manufacturer="Fairchild Semiconductor", Supplier Part Number 1=ES2DFSCT-ND, Value1=2A, Value2=0.9V
FID1 FID2 FID3: "Fiducial mark.  There is nothing to buy or mount.", Manufacturer=N/A
J1: library part CMP-0075666-1, "Header, 2.54mm, 10x1, Tin, R/A, TH", Color=Black, Manufacturer=Samtec, Supplier Part Number 1=SAM1051-10-ND, Voltage_V=550V
J2: library part CMP-0055512-1, "Terminal Block, 6x1, 2.54mm, TH", Color=Green, Current_A=6A, Manufacturer="Phoenix Contact", Supplier Part Number 1=277-1277-ND, Voltage_V=160V
J4 J5: library part CMP-0075600-2, "Header, 2.54mm, 10x2, Gold, SMT", Color=Black, Current_A=5.4A, Manufacturer=Samtec, Supplier Part Number 1=SAM8739-ND, Voltage_V=475V
LBL1: library part THT-14-423-10, "Thermal Transfer Printable Labels, 0.650\" W x 0.200\" H - 10,000 per roll", Alternate Manufacturer=-, Manufacturer=Brady, Supplier Part Number 1=2065596
Logo2: library part Pb-Free
Logo3: library part FCC_disclaimer, "FCC_disclaimer"
NT1 NT2: "Single point connection between nets."
Q1: library part CMP-0077286-1, "MOSFET, N-CH, 60 V, 75 A, AEC-Q101, PowerPAK_SO-8L", Alternate Manufacturer=None, Manufacturer=Vishay-Siliconix, Supplier Part Number 1=SQJA04EP-T1_GE3CT-ND, Value1="? ohm", Value2="35 nC"
Q2: library part "MMBTA05LT1G, ON Semiconductor", "Transistor, NPN, 60 V, 0.5 A, AEC-Q101, SOT-23", Manufacturer="ON Semiconductor", Supplier Part Number 1=MMBTA05LT1GOSCT-ND, Value1="0.5 A"
Q3 Q7: library part CMP-0000699-2, "MOSFET, 2-CH, N-CH, 40 V, 40 A, AEC-Q101, SOT1205", Alternate Manufacturer=None, Manufacturer=Nexperia, Supplier Part Number 1=568-9904-1-ND, Value2="35.4 nC"
R1: "RES, 10 k, 5%, 0.063 W, 0402", Manufacturer=Vishay-Dale, Power_W=0.063, Supplier Part Number 1=541-10KJCT-ND, TempCo="200 ppm/C", Tolerance_%=5, Value1=5%, Value2=0.063W, Value_Code=10k0, ValueDisplayed=10k
R2: "RES, 43 k, 5%, 0.063 W, 0402", Manufacturer=Vishay-Dale, Power_W=0.063, Supplier Part Number 1=541-43KJCT-ND, TempCo="200 ppm/C", Tolerance_%=5, Value1=5%, Value2=0.063W, Value_Code=43k0, ValueDisplayed=43k
R3 R4 R6 R7: library part CMP-0025951-3, "RES, 100, 1%, 0.063 W, AEC-Q200 Grade 0, 0402", Manufacturer=Vishay-Dale, Power_W=63mW, Supplier Part Number 1=541-100LCT-ND, TempCo="100 ppm/C", Tolerance_%=1%, Value2=0.063W, Value_Code=100R, ValueDisplayed=100
R5: library part CMP-0026338-2, "RES, 3.74 k, 1%, 0.063 W, AEC-Q200 Grade 0, 0402", Manufacturer=Vishay-Dale, Power_W=63mW, Supplier Part Number 1=541-3.74KLCT-ND, TempCo="100 ppm/C", Tolerance_%=1%, Value2=0.063W, Value_Code=3k74, ValueDisplayed=3.74k
R8 R11 R16 R25 R26: "RES, 10 k, 5%, 0.1 W, 0603", Manufacturer=Vishay-Dale, Power_W=0.1, Supplier Part Number 1=541-10KGCT-ND, TempCo="200 ppm/C", Tolerance_%=5, Value1=5%, Value2=0.1W, Value_Code=10k0, ValueDisplayed=10k
R9: "RES, 200, 5%, 0.1 W, 0603", Manufacturer=Vishay-Dale, Power_W=0.1, Supplier Part Number 1=541-200GCT-ND, TempCo="200 ppm/C", Tolerance_%=5, Value1=5%, Value2=0.1W, Value_Code=200R, ValueDisplayed=200
R10: library part CMP-0078669-1, "RES, 10.0 k, 1%, 0.063 W, 0402", Manufacturer="Yageo America", Power_W=63mW, Supplier Part Number 1=311-10.0KLRCT-ND, TempCo="100 ppm/C", Tolerance_%=1%, Value2=0.063W, Value_Code=10k0, ValueDisplayed=10.0k
R12: "RES, 750, 5%, 0.1 W, 0603", Manufacturer="Yageo America", Power_W=0.1, Supplier Part Number 1=311-750GRCT-ND, TempCo="100 ppm/C", Tolerance_%=5, Value1=5%, Value2=0.1W, Value_Code=750R, ValueDisplayed=750
R13: library part CMP-0017255-2, "RES, 0.003, 1%, 1 W, 1206", Manufacturer="Stackpole Electronics Inc", Power_W=1W, Supplier Part Number 1=CSNL1206FT3L00CT-ND, TempCo="50 ppm/C", Tolerance_%=1%, Value_Code=3L000, ValueDisplayed=0.003
R14: library part CMP-0023033-5, "RES, 330, 1%, 0.1 W, 0603", Manufacturer=Yageo, Power_W=100mW, Supplier Part Number 1=311-330HRCT-ND, TempCo="100 ppm/C", Tolerance_%=1%, Value2=0.1W, Value_Code=330R, ValueDisplayed=330
R15: library part CMP-0025704-4, "RES, 10, 5%, 0.25 W, AEC-Q200 Grade 0, 0603", Manufacturer=Vishay-Dale, Power_W=250mW, Supplier Part Number 1=541-10SACT-ND, TempCo="200 ppm/C", Tolerance_%=5%, Value2=0.25W, Value_Code=10R0, ValueDisplayed=10
R17: "RES, 10.0 k, 1%, 0.1 W, 0603", Manufacturer=Vishay-Dale, Power_W=0.1, Supplier Part Number 1=541-10.0KHCT-ND, TempCo="100 ppm/C", Tolerance_%=1, Value1=1%, Value2=0.1W, Value_Code=10k0, ValueDisplayed=10.0k
R18 R20: library part CMP-0026832-2, "RES, 120 k, 5%, 0.063 W, AEC-Q200 Grade 0, 0402", Manufacturer=Vishay-Dale, Power_W=63mW, Supplier Part Number 1=541-120KJCT-ND, TempCo="200 ppm/C", Tolerance_%=5%, Value2=0.063W, Value_Code=120k
R19 R21 R24: library part CMP-0026825-5, "RES, 10 k, 5%, 0.063 W, AEC-Q200 Grade 0, 0402", Manufacturer=Vishay-Dale, Power_W=63mW, Supplier Part Number 1=541-10KJCT-ND, TempCo="200 ppm/C", Tolerance_%=5%, Value2=0.063W, Value_Code=10k0, ValueDisplayed=10k
R22 R23: library part CMP-0026224-2, "RES, 294, 1%, 0.063 W, AEC-Q200 Grade 0, 0402", Manufacturer=Vishay-Dale, Power_W=63mW, Supplier Part Number 1=541-294LCT-ND, TempCo="100 ppm/C", Tolerance_%=1%, Value2=0.063W, Value_Code=294R, ValueDisplayed=294
S1 S2 S3 S4 S5: library part CMP-0002215-1, "Switch, Tactile, SPST-NO, 0.05A, 12V, SMD", CurrentRating_mA=50A, Manufacturer="Wurth Elektronik", Supplier Part Number 1=732-7007-1-ND
TB1 TB2 TB3: "Terminal Block, 5.08 mm, 2x1, TH", Color=Green, Current_A=17.5, Manufacturer="Phoenix Contact", Supplier Part Number 1=277-1263-ND, Voltage_V=400
TB4: library part CMP-0075352-1, "Terminal Block, 3.5mm, 3x1, Tin, R/A, TH", Color=Blue, Current_A=10A, Manufacturer="On-Shore Technology", Supplier Part Number 1=ED2636-ND, Voltage_V=125V
TP2 TP5: "Test Point, Compact, Black, TH", Manufacturer=Keystone, Supplier Part Number 1=36-5006-ND
TP6: "1mm Uninsulated Shorting Plug, 10.16mm spacing, TH", Manufacturer=Harwin, Supplier Part Number 1=952-1873-ND
U1: library part CMP-0013312-4, "300mA High-Voltage Ultra-Low-Iq Low-Dropout (LDO) Regulator, DGN0008D (VSSOP-8)", Alternate Manufacturer="Texas Instruments"
U2: library part CMP-0013806-3, "Full-Bridge Automotive Gate Driver, RHB0032E (VQFN-32)", Alternate Manufacturer="Texas Instruments", Alternate PartNumber=DRV8703QRHBTQ1
U3: library part CMP-0065213-4, "Automotive H-Bridge Motor Driver, PWP0024J (TSSOP-24)", Alternate Manufacturer="Texas Instruments"
U4: "Automotive Catalog 8-Channel Analog Multiplexer/Demultiplexer, PW0016A (TSSOP-16)", Alternate Manufacturer="Texas Instruments"
U5: library part CMP-0079114-1, "Local Interconnect Network (LIN) Transceiver with Dominant State Timeout, D0008A (SOIC-8)", Alternate Manufacturer="Texas Instruments", Alternate PartNumber=TLIN1029DRQ1
U6: library part CMP-0073661-1, "2.7-18-V, 2-A, 79-mO On-Resistance Load Switch with Thermal Protection, DBV0006A (SOT-23-6)", Alternate Manufacturer="Texas Instruments", Alternate PartNumber=TPS22810DBVT
U7: library part CMP-0074650-2, "Automotive Local Interconnect Network Transceiver, DRB0008F (VSON-8)", Alternate Manufacturer="Texas Instruments"
U8: library part CMP-0073692-2, "40-V/160-mO Dual Channels Smart High-Side Switch, PWP0016J (TSSOP-16)", Alternate Manufacturer="Texas Instruments"
ZZ1: library part AssemblyNoteLabel, Alternate Manufacturer=-
ZZ2 ZZ3 ZZ4: library part AssemblyNote, Alternate Manufacturer=-

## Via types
v1: diameter 19.68, hole 7.87, Top Layer to Bottom Layer, tented top, 364 vias
v2: diameter 19.68, hole 7.87, Top Layer to Bottom Layer, 148 vias
v3: diameter 19.68, hole 7.87, Top Layer to Bottom Layer, tented both sides, 21 vias

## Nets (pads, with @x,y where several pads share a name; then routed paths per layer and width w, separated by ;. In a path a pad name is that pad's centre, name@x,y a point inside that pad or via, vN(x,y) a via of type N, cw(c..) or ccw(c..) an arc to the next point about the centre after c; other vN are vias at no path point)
3p3V: C3.1 C24.1 C25.1 J1.2 J4.1 R8.2 R9.1 R11.1 R12.2 R16.1 R25.2 R26.1 U1.8 U4.16 U6.1 U7.8 | length 5753.7
  Top Layer w10: v2(1710,540) J4.1@1800,450 ; C24.1@3554.37,645.87 3620,645.87 ; U6.1@3620,607.09 3620,645.87 ; U7.8@3698.39,774.88 3700,773.27 3700,700 3645.87,645.87 3620,645.87 ; U1.8@3921.61,997.6 3921.61,1071.61 C3.1@3930,1080 ; C3.1@3938.5,1088.5 R9.1@3938.5,1160 3978.5,1200 U4.16@4200,1200
  Top Layer w12: 1872.44,1082.44 R12.2@1872.44,1840
  Top Layer w20: v2(1710,1080) C3.1@3930,1080 ; v2(3420,660) 3448.5,631.5 C24.1@3540,631.5
  Bottom Layer w12: J1.2@1030,160 1410,540 v2(1710,540)
  Bottom Layer w20: v2(1710,540) 1710,796.29 1707.77,798.52 1707.77,821.48 1710,823.71 v2(1710,1080) ; v2(3420,660) v3(3420,1080)
AVDD: C7.1 U2.14 U2.15 | length 109.5
  Top Layer w10: C7.1@5300,1033.62 5327.56,1061.18 5327.56,1085.48 5327.7,1085.63 5352.01,1085.63 5352.24,1085.87 U2.15@5352.24,1087.52 U2.14@5352.24,1107.2
DISABLE: J4.10 U3.9 | length 3686.6
  Top Layer w8: J4.10@2200,598 v2(2200,720) ; v2(2200,1350) 2220,1370 4590,1370 4719.02,1240.98 U3.9@4719.02,887.08
  Bottom Layer w8: v2(2200,720) v2(2200,1350)
DVDD: C8.1 U2.12 | length 57.6
  Top Layer w8: C8.1@5300,1133.62 5312.95,1146.57 U2.12@5352.24,1146.57
GH1: Q3.4 U2.18 | length 621.2
  Top Layer w8: Q3.4@5456.06,520 v2(5490,520)
  Top Layer w10: v2(5360,930) 5360,985.59 5397.52,1023.11 U2.18@5397.52,1037.83
  Bottom Layer w10: v2(5360,930) 5360,650 v2(5490,520)
GH2: Q3.2 U2.26 | length 920.7
  Top Layer w10: v1(5360,480) Q3.2@5360,516.06 ; U2.26@5542.01,1086.73 v2(5566.73,1086.73)
  Bottom Layer w10: v1(5360,480) 5500,480 5670,650 5670,983.46 v2(5566.73,1086.73)
GL1: Q7.4 U2.20 | length 346
  Top Layer w10: U2.20@5436.89,1042.24 5436.89,996.43 5422.36,981.91 5422.36,972.36 v2(5406.73,956.73) 5406.73,933.27 v2(5540,800) Q7.4@5540,763.94
GL2: Q7.2 U2.24 | length 329.9
  Top Layer w10: U2.24@5515.63,1042.24 5515.71,1042.24 5515.71,1027.76 v2(5530,1013.46) ; Q7.2@5640,763.94 v2(5640,800)
  Bottom Layer w10: v2(5530,1013.46) 5530,910 v2(5640,800)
